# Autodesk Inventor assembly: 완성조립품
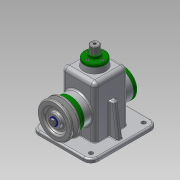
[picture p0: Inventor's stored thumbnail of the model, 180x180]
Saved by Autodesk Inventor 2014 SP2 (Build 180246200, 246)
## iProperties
Created: 2016-08
Part Number: 완성조립품
Document SubType Name: Assembly
Designer: user
Author: user
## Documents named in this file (18)
- C:\Users\user\Desktop\460820V1009\완성조립품.iam
- C:\Users\user\Desktop\460820V1009\본체.ipt
- C:\Users\user\Desktop\460820V1009\뒤커버.ipt
- C:\Users\user\Desktop\460820V1009\앞커버.ipt
- C:\Users\user\Desktop\460820V1009\베어링 15 x 35 x 11.ipt
- C:\Users\user\Desktop\460820V1009\편심축.ipt
- C:\Users\user\Desktop\460820V1009\키 5 x 5 x 14.ipt
- C:\Users\user\Desktop\460820V1009\V-벨트풀리.ipt
- C:\Users\user\Desktop\460820V1009\볼트 M6 x 12.ipt
- C:\Users\user\Desktop\460820V1009\와셔.ipt
- C:\Users\user\Desktop\460820V1009\볼트 M4 x 10.ipt
- C:\Users\user\Desktop\460820V1009\멈춤링 15 x 1.ipt
- C:\Users\user\Desktop\460820V1009\상부부시.ipt
- C:\Users\user\Desktop\460820V1009\볼트 M3 x 8.ipt
- C:\Users\user\Desktop\460820V1009\링크.ipt
- C:\Users\user\Desktop\460820V1009\슬라이드바.ipt
- C:\Users\user\Desktop\460820V1009\고정핀.ipt
- C:\Users\user\Desktop\460820V1009\멈춤링 6 x 5.ipt
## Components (15 placed, 5 different names)
1. V-벨트풀리:1 — 각도:1
2. ISO 4018 M6 x 12:1 — 강체:1
3. 고정핀:1
4. ISO 4762 M4 x 10:1 — 강체:2
5. ISO 4762 M4 x 10:3
6. ISO 4762 M4 x 10:4
7. ISO 4762 M4 x 10:5
8. ISO 4762 M4 x 10:2 — 강체:3
9. ISO 4762 M4 x 10:6
10. ISO 4762 M4 x 10:7
11. ISO 4762 M4 x 10:8
12. ISO 4762 M3 x 8:1 — 강체:4
13. ISO 4762 M3 x 8:2
14. ISO 4762 M3 x 8:3
15. ISO 4762 M3 x 8:4
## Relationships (5: WeldJoint 4, Angle 1)
- 각도:1 [Angle]: V-벨트풀리:1
- 강체:1 [WeldJoint]: ISO 4018 M6 x 12:1
- 강체:2 [WeldJoint]: ISO 4762 M4 x 10:1
- 강체:3 [WeldJoint]: ISO 4762 M4 x 10:2
- 강체:4 [WeldJoint]: ISO 4762 M3 x 8:1
